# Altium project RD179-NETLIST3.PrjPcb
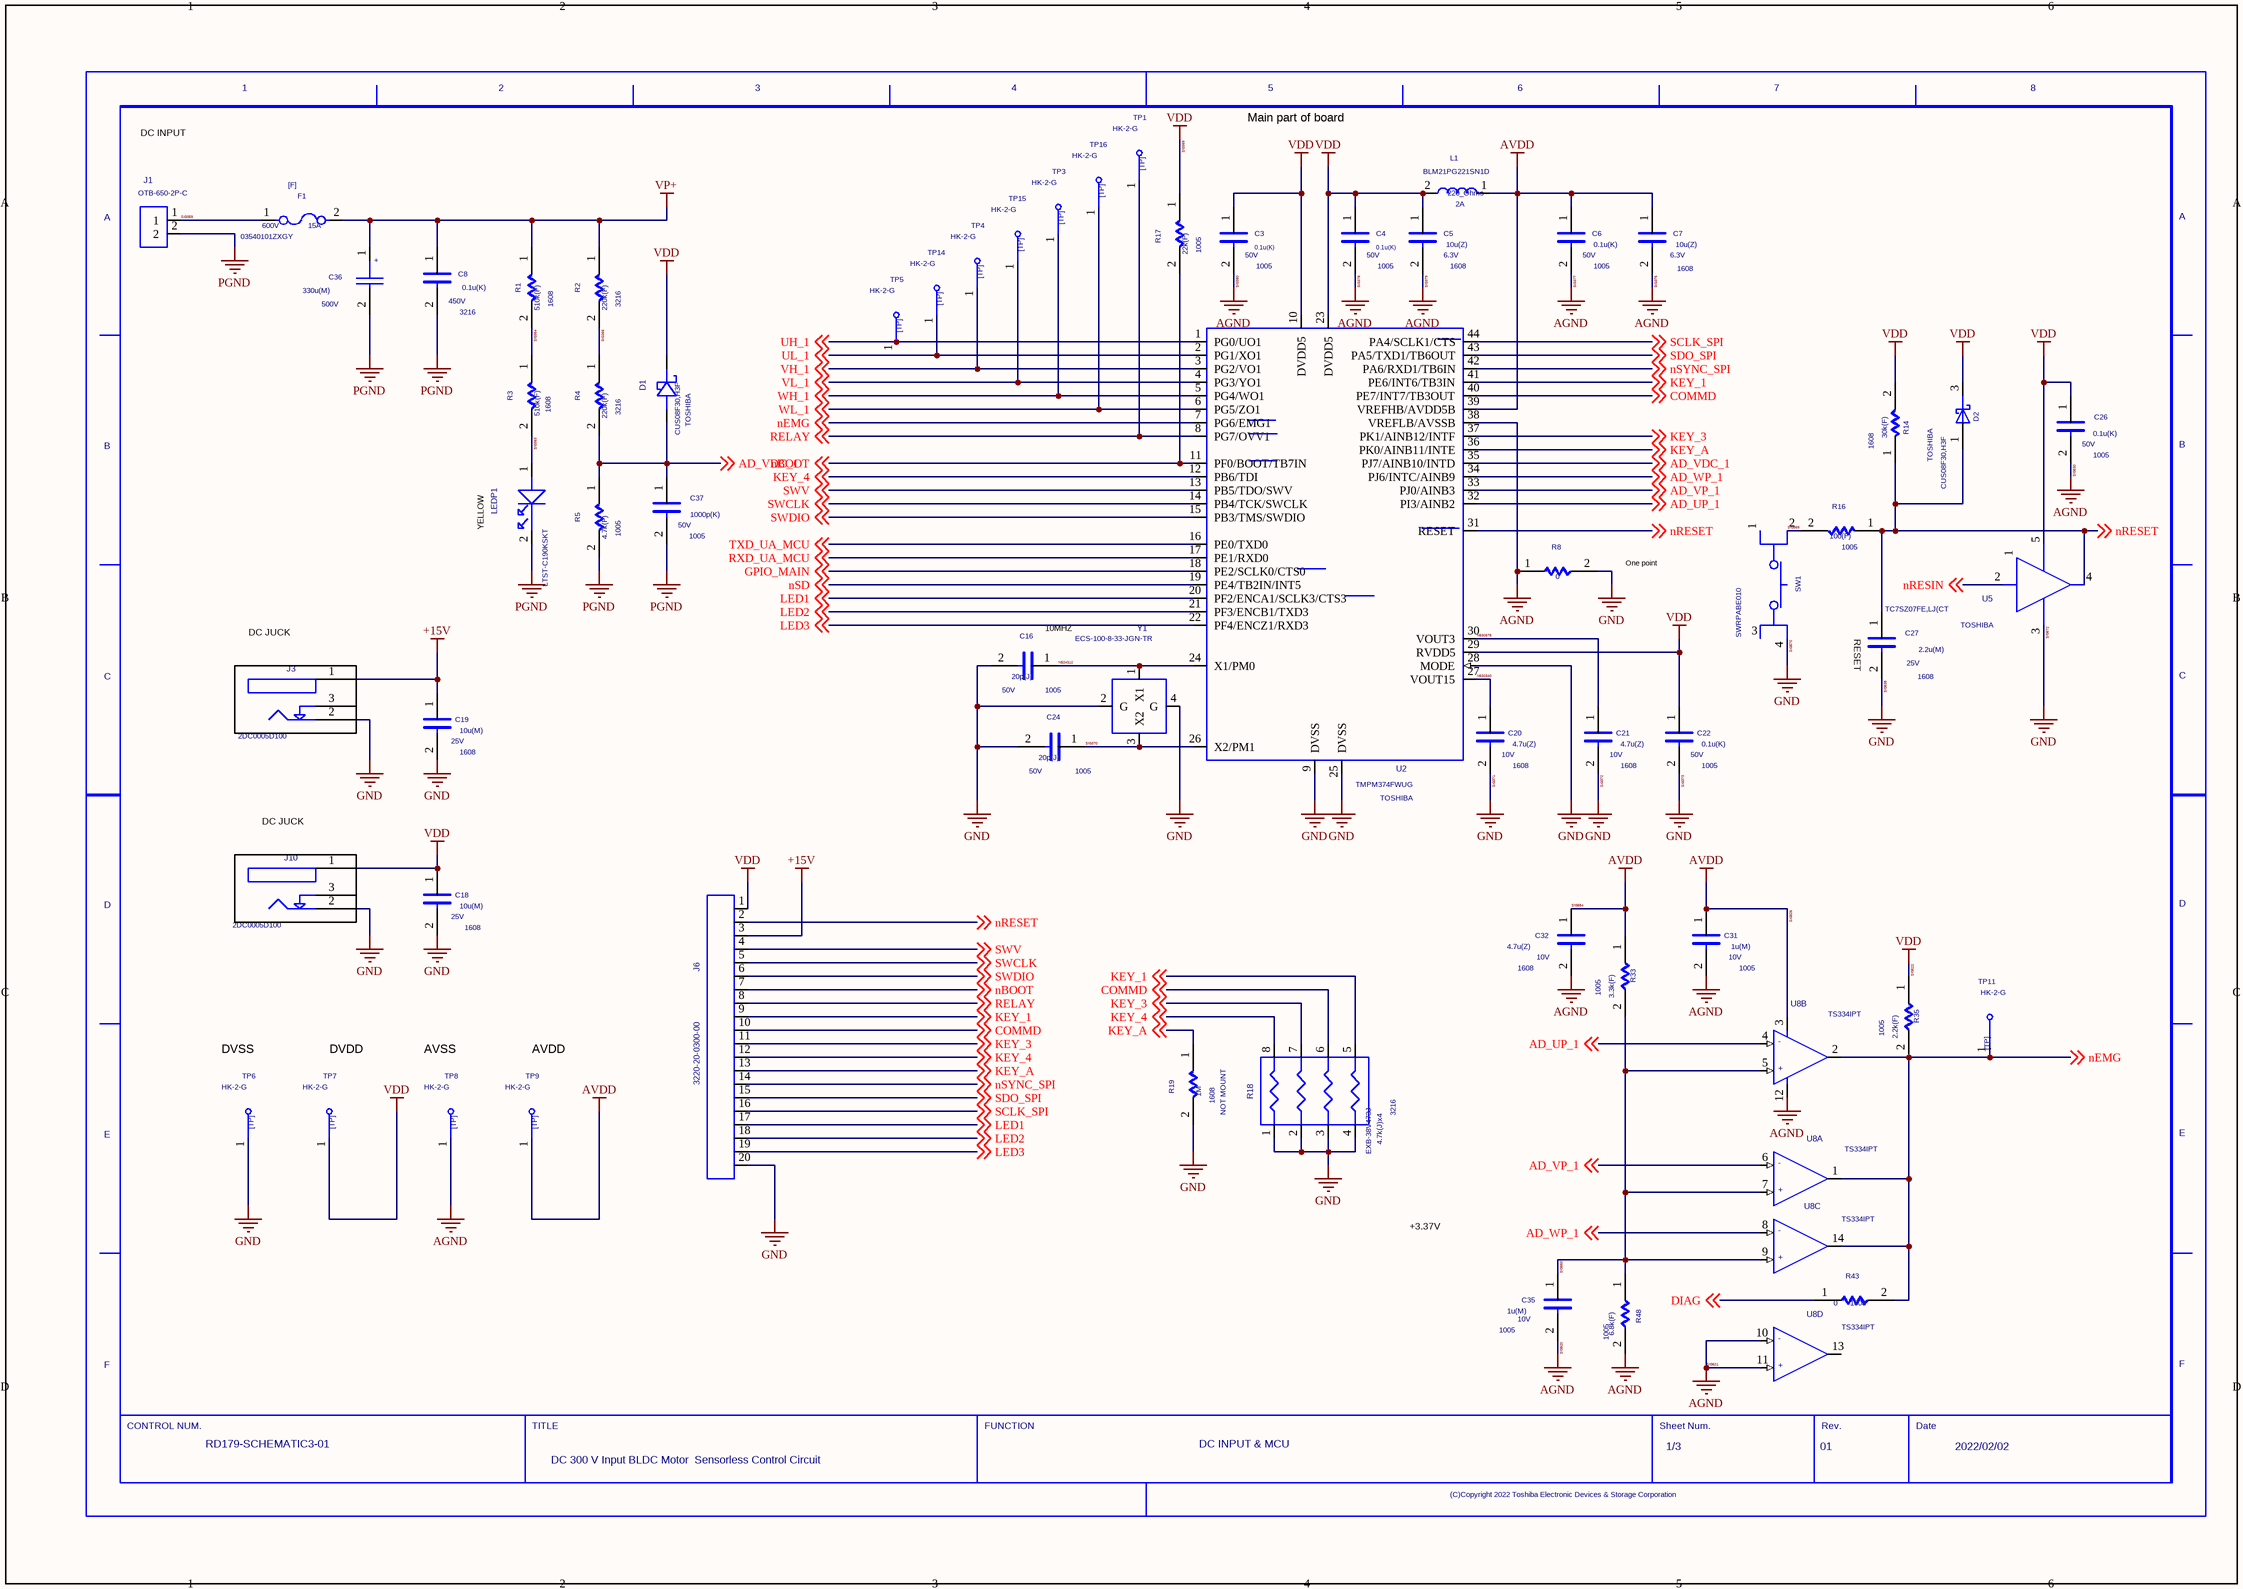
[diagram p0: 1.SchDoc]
3 sheets, 148 parts. Net scope: global (net labels, ports and power ports of the same name join across sheets).
Sheets:
  1.SchDoc
  2.SchDoc
  3.SchDoc

## Sheet 1.SchDoc
size 420 x 297 mm

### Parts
(Parts that share a designator on the sheet are numbered #1, #2 ... from top to bottom, then left to right.)
C3  SIZECODESMD: 1005  VAL2: 50V  VAL1: 0.1u(K)  (hidden comment: C)
C4  SIZECODESMD: 1005  VAL2: 50V  VAL1: 0.1u(K)  (hidden comment: C)
C5  SIZECODESMD: 1608  VAL2: 6.3V  VAL1: 10u(Z)  (hidden comment: C)
C6  SIZECODESMD: 1005  VAL2: 50V  VAL1: 0.1u(K)  (hidden comment: C)
C7  SIZECODESMD: 1608  VAL2: 6.3V  VAL1: 10u(Z)  (hidden comment: C)
C8  SIZECODESMD: 3216  VAL2: 450V  VAL1: 0.1u(K)  (hidden comment: C)
C16  SIZECODESMD: 1005  VAL2: 50V  VAL1: 20p(J)  (hidden comment: C)
C18  SIZECODESMD: 1608  VAL2: 25V  VAL1: 10u(M)  (hidden comment: C)
C19  SIZECODESMD: 1608  VAL2: 25V  VAL1: 10u(M)  (hidden comment: C)
C20  SIZECODESMD: 1608  VAL2: 10V  VAL1: 4.7u(Z)  (hidden comment: C)
C21  SIZECODESMD: 1608  VAL2: 10V  VAL1: 4.7u(Z)  (hidden comment: C)
C22  SIZECODESMD: 1005  VAL2: 50V  VAL1: 0.1u(K)  (hidden comment: C)
C24  SIZECODESMD: 1005  VAL2: 50V  VAL1: 20p(J)  (hidden comment: C)
C26  SIZECODESMD: 1005  VAL2: 50V  VAL1: 0.1u(K)  (hidden comment: C)
C27  SIZECODESMD: 1608  VAL2: 25V  VAL1: 2.2u(M)  (hidden comment: C)
C31  SIZECODESMD: 1005  VAL2: 10V  VAL1: 1u(M)  (hidden comment: C)
C32  SIZECODESMD: 1608  VAL2: 10V  VAL1: 4.7u(Z)  (hidden comment: C)
C35  SIZECODESMD: 1005  VAL2: 10V  VAL1: 1u(M)  (hidden comment: C)
C36  VAL2: 500V  VAL1: 330u(M)  (hidden comment: CP)
C37  SIZECODESMD: 1005  VAL2: 50V  VAL1: 1000p(K)  (hidden comment: C)
D1  USERCOMPTEXT3: TOSHIBA  VAL3: CUS08F30,H3F  (hidden comment: CUS08F30)
D2  USERCOMPTEXT3: TOSHIBA  VAL3: CUS08F30,H3F  (hidden comment: SBD)
F1  VAL3: 03540101ZXGY  VAL2: 15A  VAL1: 600V  (hidden comment: F)
J1  OTB-650-2P-C
J3  VAL3: 2DC0005D100  (hidden comment: DCJACK)
J6  3220-20-0300-00
J10  VAL3: 2DC0005D100  (hidden comment: DCJACK)
L1  VAL3: BLM21PG221SN1D  VAL2: 2A  VAL1: 220_Ohms  (hidden comment: L)
LEDP1  LTST-C190KSKT  [LED]
R1  SIZECODESMD: 1608  VAL1: 510k(F)  (hidden comment: R)
R2  SIZECODESMD: 3216  VAL1: 220k(F)  (hidden comment: R)
R3  SIZECODESMD: 1608  VAL1: 510k(F)  (hidden comment: R)
R4  SIZECODESMD: 3216  VAL1: 220k(F)  (hidden comment: R)
R5  SIZECODESMD: 1005  VAL1: 4.7k(F)  (hidden comment: R)
R8  VAL1: 0  (hidden comment: R)
R14  SIZECODESMD: 1608  VAL1: 30k(F)  (hidden comment: R)
R16  SIZECODESMD: 1005  VAL1: 100(F)  (hidden comment: R)
R17  SIZECODESMD: 1005  VAL1: 22k(F)  (hidden comment: R)
R18  SIZECODESMD: 3216  VAL1: 4.7k(J)x4  (hidden comment: EXB-38V473J)
R19  NOTMOUNT: NOT MOUNT  SIZECODESMD: 1608  VAL1: 1M  (hidden comment: R)
R33  SIZECODESMD: 1005  VAL1: 3.3k(F)  (hidden comment: R)
R35  SIZECODESMD: 1005  VAL1: 2.2k(F)  (hidden comment: R)
R43  SIZECODESMD: 1608  VAL1: 0  (hidden comment: R)
R48  SIZECODESMD: 1005  VAL1: 6.8k(F)  (hidden comment: R)
SW1  SWRPABE010
TP1  VAL3: HK-2-G  (hidden comment: TP)
TP3  VAL3: HK-2-G  (hidden comment: TP)
TP4  VAL3: HK-2-G  (hidden comment: TP)
TP5  VAL3: HK-2-G  (hidden comment: TP)
TP6  VAL3: HK-2-G  (hidden comment: TP)
TP7  VAL3: HK-2-G  (hidden comment: TP)
TP8  VAL3: HK-2-G  (hidden comment: TP)
TP9  VAL3: HK-2-G  (hidden comment: TP)
TP11  VAL3: HK-2-G  (hidden comment: TP)
TP14  VAL3: HK-2-G  (hidden comment: TP)
TP15  VAL3: HK-2-G  (hidden comment: TP)
TP16  VAL3: HK-2-G  (hidden comment: TP)
U2  USERCOMPTEXT3: TOSHIBA  (hidden comment: TMPM374FWUG)
U5  USERCOMPTEXT3: TOSHIBA  VAL3: TC7SZ07FE,LJ(CT  (hidden comment: SN74LVC1G07DRLR_1)
U8  VAL3: TS334IPT  (hidden comment: LMV339IPT_2)  (parts A,B,C,D of 4)
U?#1  DATE: 2022/02/02  FUNCTION: DC INPUT & MCU  TITLE: DC 300 V Input BLDC Motor / Sensorless Control Circuit  DRAWINGNUMBER: RD179-SCHEMATIC3-01  REVISION: 01  SHEETNUMBER: 1/3  (hidden comment: WAKU_DEF100)
Y1  VAL3: ECS-100-8-33-JGN-TR  (hidden comment: XTAL_ECS_100_8_33_10_000MHZ)

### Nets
+15V: C19.1 J3.1(+5V) J6.3  [project net SIG462]
PGND: C8.2 C36.2 C37.2 J1.2 LEDP1.2(Cathode) R5.2  [project net SIG567]
SIG369: C3.1 C4.1 C5.1 C18.1 C22.1 C26.1 D1.3(CATHODE) D2.3(C) J6.1 J10.1(+5V) L1.2 R14.2 R17.1 R35.1 TP7.1 U2.10(DVDD5) U2.23(DVDD5) U2.29(RVDD5) U5.5(VCC)  [also labelled SIG522, VDD]
SIG371: C16.2 C18.2 C19.2 C20.2 C21.2 C22.2 C24.2 C27.2 J3.2(GND) J6.20 J10.2(GND) R8.2 R18.1 R18.2 R18.3 R18.4 R19.2 SW1.4 TP6.1 U2.9(DVSS) U2.25(DVSS) U2.28(MODE) U5.3(GND) Y1.2(G) Y1.4(G)  [also labelled GND, SIG372, SIG373, SIG535, SIG570, SIG572]
SIG376: C3.2 C4.2 C5.2 C6.2 C7.2 C26.2 C31.2 C32.2 C35.2 R8.1 R48.2 TP8.1 U2.38(VREFLB/AVSSB) U8.10 U8.11 U8.12(GND)  [also labelled AGND, SIG377, SIG378, SIG379, SIG380, SIG520, SIG521, SIG530]
SIG526: C6.1 C7.1 C31.1 C32.1 L1.1 R33.1 TP9.1 U2.39(VREFHB/AVDD5B) U8.3(VCC)  [also labelled AVDD, SIG554]
VP+: C8.1 C36.1 F1.2 R1.1 R2.1  [project net SIG477]
AD_UP_1: U2.32(PI3/AINB2) U8.4(IN-) ; off-sheet AD_UP_1
AD_VDC_1: C37.1 D1.1(ANODE) R4.2 R5.1 U2.35(PJ7/AINB10/INTD) ; off-sheet AD_VDC_1
AD_VP_1: U2.33(PJ0/AINB3) U8.6 ; off-sheet AD_VP_1
AD_WP_1: U2.34(PJ6/INTC/AINB9) U8.8 ; off-sheet AD_WP_1
COMMD: J6.10 R18.6 U2.40(PE7/INT7/TB3OUT) ; off-sheet COMMD
DIAG: R43.1 ; off-sheet DIAG
GPIO_MAIN: U2.18(PE2/SCLK0/CTS0) ; off-sheet GPIO_MAIN
KEY_1: J6.9 R18.5 U2.41(PE6/INT6/TB3IN) ; off-sheet KEY_1
KEY_3: J6.11 R18.7 U2.37(PK1/AINB12/INTF) ; off-sheet KEY_3
KEY_4: J6.12 R18.8 U2.12(PB6/TDI) ; off-sheet KEY_4
KEY_A: J6.13 R19.1 U2.36(PK0/AINB11/INTE) ; off-sheet KEY_A
LED1: J6.17 U2.20(PF2/ENCA1/SCLK3/CTS3) ; off-sheet LED1
LED2: J6.18 U2.21(PF3/ENCB1/TXD3) ; off-sheet LED2
LED3: J6.19 U2.22(PF4/ENCZ1/RXD3) ; off-sheet LED3
N524312: C16.1 U2.24(X1/PM0) Y1.1(X1)
N530340: C20.1 U2.27(VOUT15)
N530678: C21.1 U2.30(VOUT3)
nBOOT: J6.7 R17.2 U2.11(PF0/BOOT/TB7IN) ; off-sheet nBOOT
nEMG: R35.2 R43.2 TP11.1 U2.7(PG6/EMG1) U8.1 U8.2(OUT) U8.14 ; off-sheet nEMG
nRESET: C27.1 D2.1(A) J6.2 R14.1 R16.1 U2.31(RESET) U5.4(OUTY) ; off-sheet nRESET
nSD: U2.19(PE4/TB2IN/INT5) ; off-sheet nSD
nSYNC_SPI: J6.14 U2.42(PA6/RXD1/TB6IN) ; off-sheet nSYNC_SPI
RELAY: J6.8 TP1.1 U2.8(PG7/OVV1) ; off-sheet RELAY
RXD_UA_MCU: U2.17(PE1/RXD0) ; off-sheet RXD_UA_MCU
SCLK_SPI: J6.16 U2.44(PA4/SCLK1/CTS) ; off-sheet SCLK_SPI
SDO_SPI: J6.15 U2.43(PA5/TXD1/TB6OUT) ; off-sheet SDO_SPI
SIG359: F1.1 J1.1
SIG363: LEDP1.1(Anode) R3.2
SIG364: R1.2 R3.1
SIG366: R2.2 R4.1
SIG370: C24.1 U2.26(X2/PM1) Y1.3(X2)
SIG553: C35.1 R33.2 R48.1 U8.5(IN+) U8.7 U8.9
SIG569: R16.2 SW1.2
SIG571: U5.2(INA) ; off-sheet nRESIN  [also labelled nRESIN]
SWCLK: J6.5 U2.14(PB4/TCK/SWCLK) ; off-sheet SWCLK
SWDIO: J6.6 U2.15(PB3/TMS/SWDIO) ; off-sheet SWDIO
SWV: J6.4 U2.13(PB5/TDO/SWV) ; off-sheet SWV
TXD_UA_MCU: U2.16(PE0/TXD0) ; off-sheet TXD_UA_MCU
UH_1: TP5.1 U2.1(PG0/UO1) ; off-sheet UH_1
UL_1: TP14.1 U2.2(PG1/XO1) ; off-sheet UL_1
VH_1: TP4.1 U2.3(PG2/VO1) ; off-sheet VH_1
VL_1: TP15.1 U2.4(PG3/YO1) ; off-sheet VL_1
WH_1: TP3.1 U2.5(PG4/WO1) ; off-sheet WH_1
WL_1: TP16.1 U2.6(PG5/ZO1) ; off-sheet WL_1

Not connected (* = marked no-connect by the designer): J3 3(NC); J10 3(NC); SW1 1 3; U5 1; U8 13

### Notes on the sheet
- Main part of board
- DC INPUT
  120V-340V
- (near LEDP1) YELLOW
- One point
  ground
- (near J3) DC JUCK
  +15V
- (near C16) 10MHZ
- (near C27) RESET
- (near J10) DC JUCK
  +5V
- DVSS
- DVDD
- AVSS
- AVDD
- +3.37V
  (2.89A)

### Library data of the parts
C3 C4 C6 C16 C22 C24 C26 C31 C35 C37 = C: OriginalSymbolOrigin: (2540,7620); COMP: CRC-1005-DEF
C5 C7 C18-C21 C27 C32 = C: OriginalSymbolOrigin: (2540,7620); COMP: CRC-1608-DEF
C8 = C: OriginalSymbolOrigin: (2540,7620); COMP: CC-3216-DEF
C36 = CP: SAVEAREA0: -1450,-153,20294,13055; SAVECOUNT: 52; TIME: 15:02:55; UPDATEUSER: fukuda-y; UPDATETIME: 16:13:42; OriginalSymbolOrigin: (2540,10160); COMP: DDC-3000-00
D1 = DIODE_SB1003M3: COMP: CD-USC-05; TIME: 16:32:01; UPDATEUSER: t5459927; SAVECOUNT: 1; OriginalSymbolOrigin: (0,0); INSTANCENAME: I16849034
D2 = SBD: SAVEAREA0: -4630,-153,17114,13055; TIME: 14:49:55; UPDATEUSER: fukuda-y; UPDATETIME: 08:16:22; SAVECOUNT: 9; OriginalSymbolOrigin: (5080,5080); COMP: CD-USC-05
F1 = F: OriginalSymbolOrigin: (2540,5080); COMP: DFU-3512-00
J1 = OTB_650_2P_C: COMP: OTB-650-2P_R00; TIME: 16:32:00; UPDATEUSER: t5459927; SAVECOUNT: 1; SAVEAREA0: -4443,-7788,6738,409; OriginalSymbolOrigin: (0,0); INSTANCENAME: I00689
J3 = DCJACK: COMP: 2DC-0005D100_R00; ORDER: 0; TIME: 16:32:01; UPDATEUSER: t5459927; SAVECOUNT: 1; SAVEAREA0: -1163,-13964,20286,1761; OriginalSymbolOrigin: (0,0); INSTANCENAME: I16855658
J6 = CON20: COMP: 3220-20-0300-00_R00; TIME: 16:32:01; UPDATEUSER: t5459927; SAVECOUNT: 1; SAVEAREA0: -36272,-54408,42011,2984; OriginalSymbolOrigin: (0,0); INSTANCENAME: I17020784
J10 = DCJACK: COMP: 2DC-0005D100_R00; ORDER: 0; TIME: 16:32:01; UPDATEUSER: t5459927; SAVECOUNT: 1; SAVEAREA0: -1163,-13964,20286,1761; OriginalSymbolOrigin: (0,0); INSTANCENAME: I17047111
L1 = L: OriginalSymbolOrigin: (2540,5080); COMP: CL-2125-DEF
LEDP1 = LED_3RED: COMP: LTST-C190_R00; TIME: 16:32:00; UPDATEUSER: t5459927; SAVECOUNT: 1; OriginalSymbolOrigin: (0,0); INSTANCENAME: I16843725
R1 R3 = R: OriginalSymbolOrigin: (5080,5080); VAL2: 250mW; COMP: CRC-1608-DEF
R2 R4 = R: OriginalSymbolOrigin: (5080,5080); VAL2: 250mW; COMP: CR-3216-DEF
R5 = R: OriginalSymbolOrigin: (5080,5080); VAL2: 63mW; COMP: CRC-1005-DEF
R8 = R: OriginalSymbolOrigin: (5080,5080); COMP: CX-0002-75
R14 = R: OriginalSymbolOrigin: (5080,5080); VAL2: 100mW; COMP: CRC-1608-58
R16 R17 R33 R35 = R: OriginalSymbolOrigin: (5080,5080); VAL2: 100mW; COMP: CRC-1005-DEF
R18 = EXB_38V: COMP: CRA-3216-33; TIME: 16:32:00; UPDATEUSER: t5459927; SAVECOUNT: 1; SAVEAREA0: -8920,-20726,20901,1136; OriginalSymbolOrigin: (0,0); VAL2: 63w; INSTANCENAME: I17038151
R19 R43 = R: OriginalSymbolOrigin: (5080,5080); VAL2: 100mW; COMP: CRC-1608-DEF
R48 = R: OriginalSymbolOrigin: (5080,5080); VAL2: 63mW; COMP: CRC-1005-12
SW1 = SWRPABE010: CDBNAME: S3; MONOCODE: E00000387; DEVICENAME: SKRELEE010; SAVECOUNT: 12; SAVEAREA0: -20086,-19151,40623,8833; TIME: 17:27:08; UPDATEUSER: t5459927; UPDATETIME: 11:11:13; OriginalSymbolOrigin: (-2540,-2540); COMP: SKRPABE010_R01
TP1 TP3-TP9 TP11 TP14-TP16 = TP: TIME: 16:12:21; UPDATEUSER: fukuda-y; UPDATETIME: 16:18:11; SAVECOUNT: 2; SAVEAREA0: -242,-92,12810,7836; OriginalSymbolOrigin: (0,7620)
U2 = TMPM374FWUG: TIME: 16:32:00; UPDATEUSER: t5459927; UPDATETIME: 15:11:09; SAVECOUNT: 3; SAVEAREA0: -44310,-81679,90078,-7285; OriginalSymbolOrigin: (0,0)
U5 = SN74LVC1G07DRLR_1: COMP: TC7SZ07FE; ORDER: 0; TIME: 16:32:01; UPDATEUSER: t5459927; UPDATETIME: 09:28:13; SAVECOUNT: 2; SAVEAREA0: -35105,-23290,44922,13600; OriginalSymbolOrigin: (-2540,2540)
U8 = LMV339IPT_2: TIME: 16:31:59; UPDATEUSER: t5459927; UPDATETIME: 15:18:09; SAVECOUNT: 11; SAVEAREA0: -12314,3023,22191,18929; OriginalSymbolOrigin: (0,0); CaptureCellPackProp: LMV339IPT_2A; FUNCN: TS334IPT_2
U?#1 = WAKU_DEF100: PLOTTIME: HH:MM; SAVEAREA0: 147884,-66467,487065,89883; TIME: 14:30:25; UPDATEUSER: t5459927; UPDATETIME: 12:53:04; SAVECOUNT: 7; OriginalSymbolOrigin: (10160,284480)
Y1 = XTAL_ECS_100_8_33_10_000MHZ: COMP: CXL-3225-68; ORDER: 1; TIME: 16:32:00; UPDATEUSER: t5459927; UPDATETIME: 15:12:21; SAVECOUNT: 3; SAVEAREA0: -55012,-32573,65020,22757; OriginalSymbolOrigin: (0,0)

## Sheet 2.SchDoc
size 420 x 297 mm
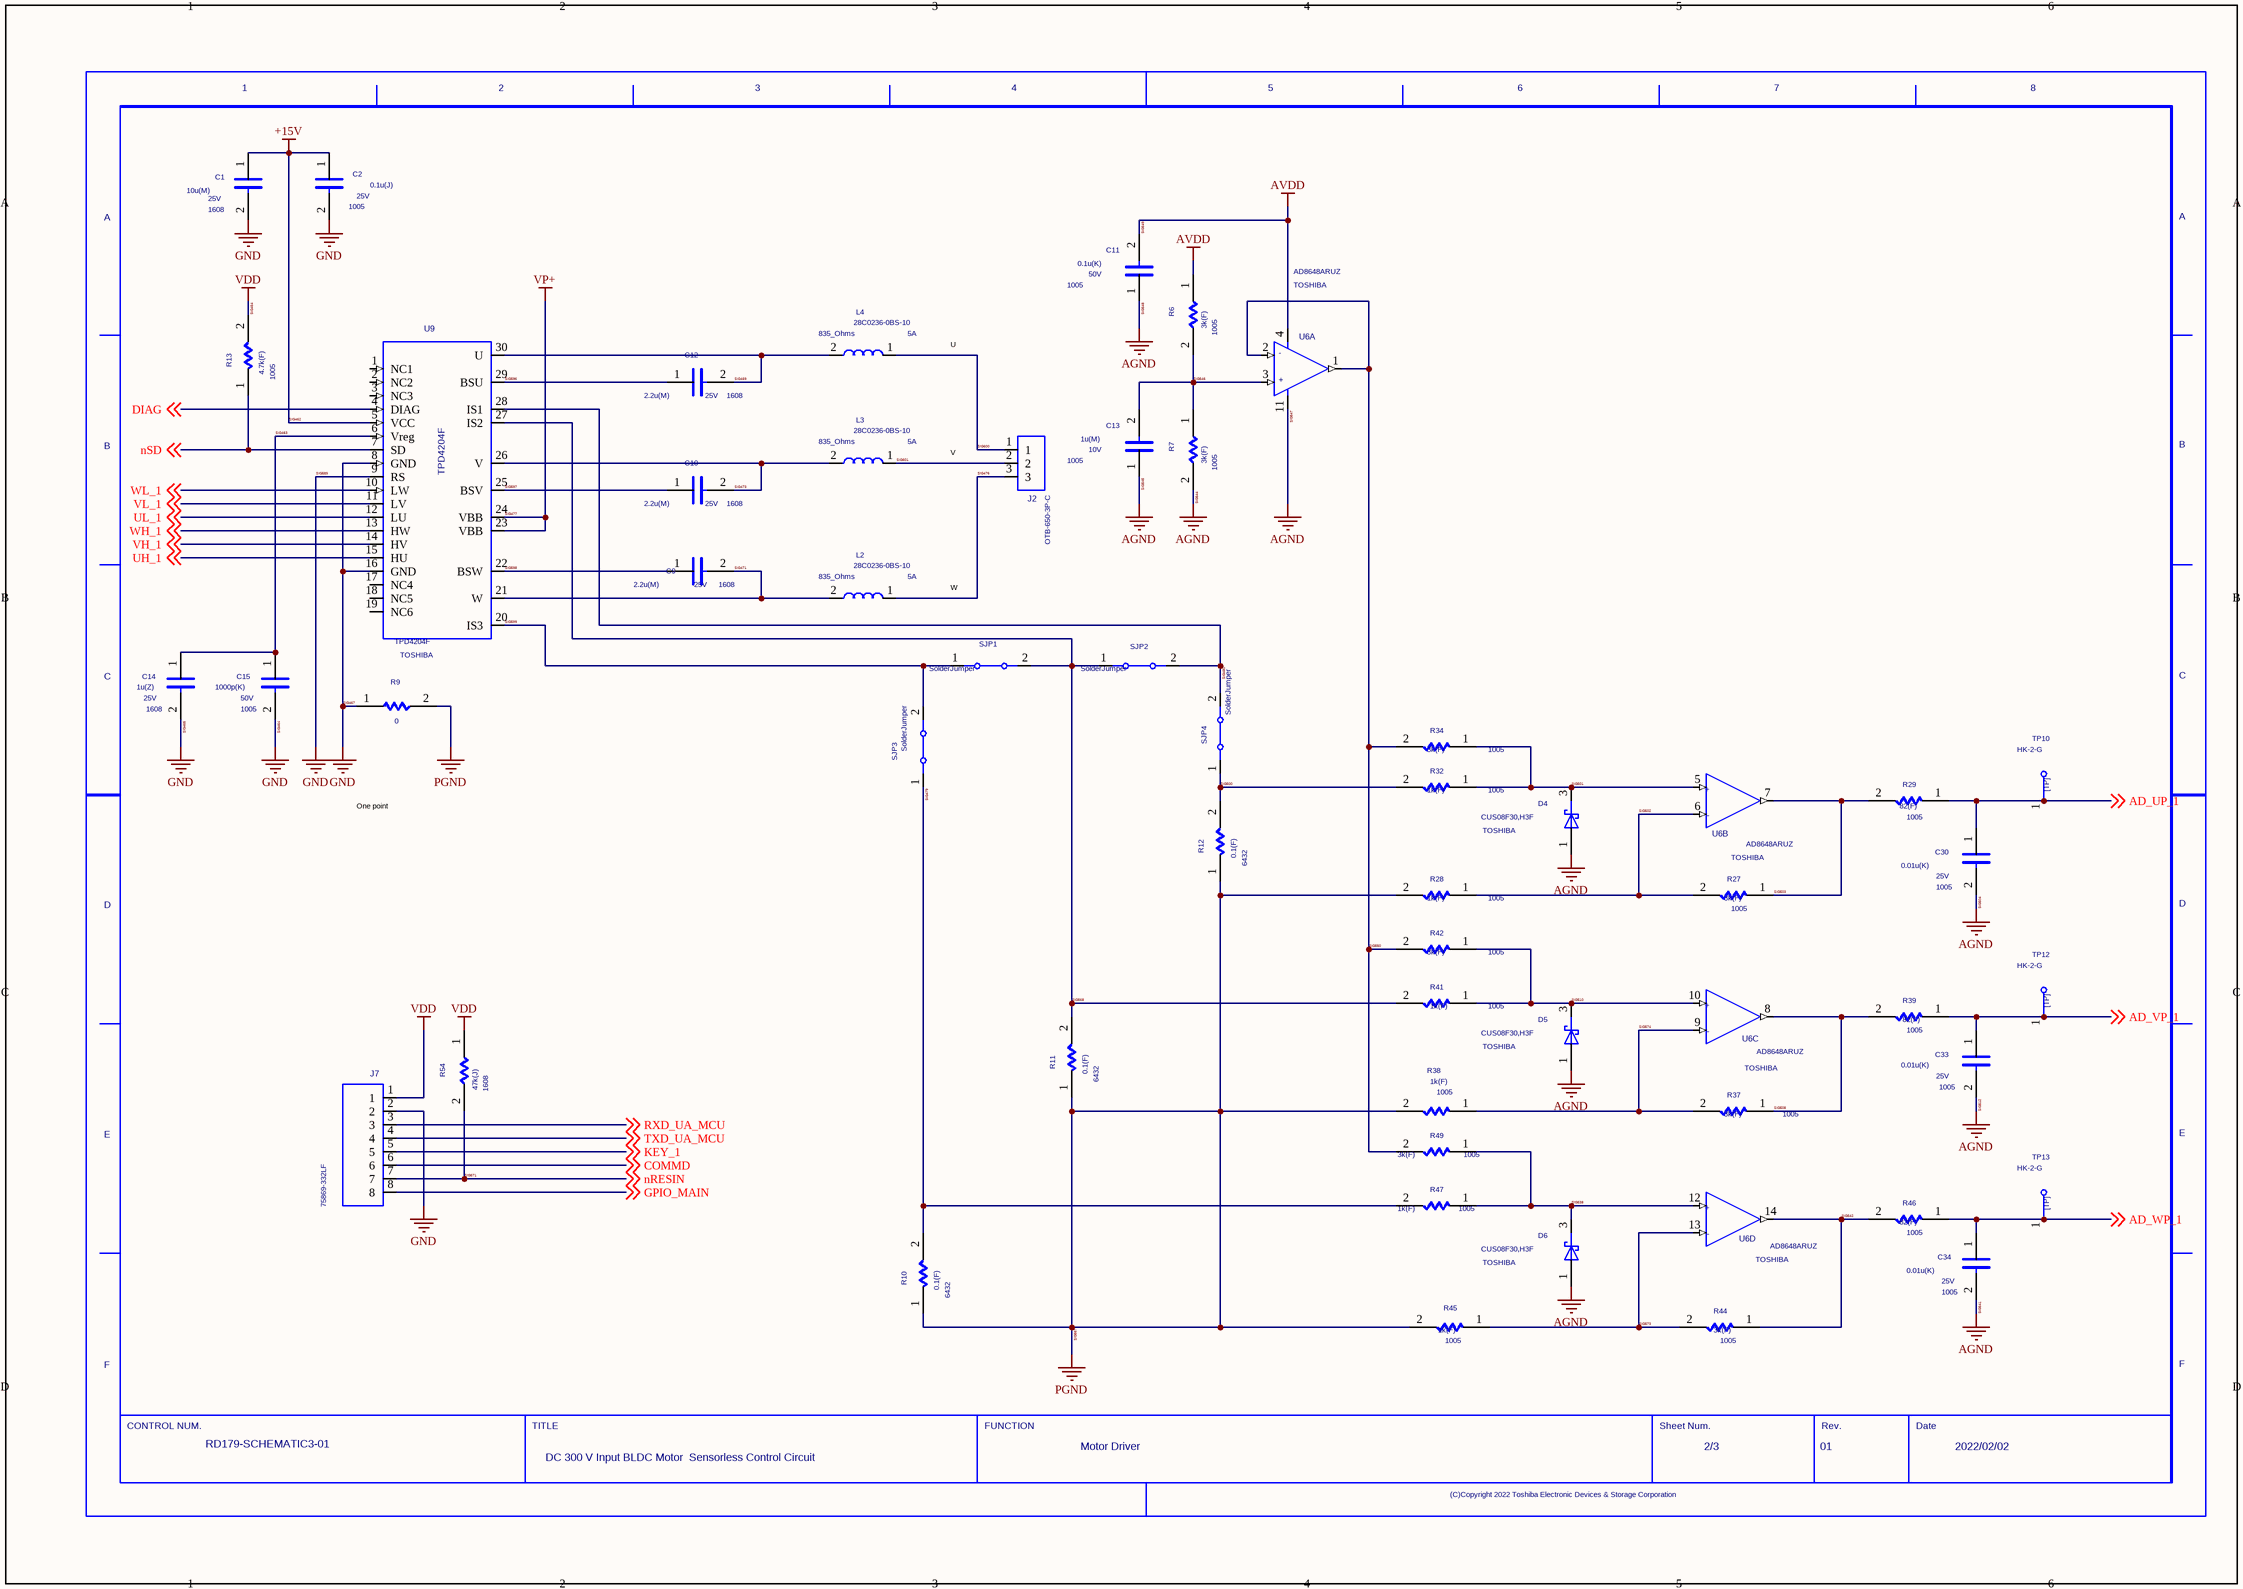
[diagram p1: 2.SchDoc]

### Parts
(Parts that share a designator on the sheet are numbered #1, #2 ... from top to bottom, then left to right.)
C1  SIZECODESMD: 1608  VAL2: 25V  VAL1: 10u(M)  (hidden comment: C)
C2  SIZECODESMD: 1005  VAL2: 25V  VAL1: 0.1u(J)  (hidden comment: C)
C9  SIZECODESMD: 1608  VAL2: 25V  VAL1: 2.2u(M)  (hidden comment: C)
C10  SIZECODESMD: 1608  VAL2: 25V  VAL1: 2.2u(M)  (hidden comment: C)
C11  SIZECODESMD: 1005  VAL2: 50V  VAL1: 0.1u(K)  (hidden comment: C)
C12  SIZECODESMD: 1608  VAL2: 25V  VAL1: 2.2u(M)  (hidden comment: C)
C13  SIZECODESMD: 1005  VAL2: 10V  VAL1: 1u(M)  (hidden comment: C)
C14  SIZECODESMD: 1608  VAL2: 25V  VAL1: 1u(Z)  (hidden comment: C)
C15  SIZECODESMD: 1005  VAL2: 50V  VAL1: 1000p(K)  (hidden comment: C)
C30  SIZECODESMD: 1005  VAL2: 25V  VAL1: 0.01u(K)  (hidden comment: C)
C33  SIZECODESMD: 1005  VAL2: 25V  VAL1: 0.01u(K)  (hidden comment: C)
C34  SIZECODESMD: 1005  VAL2: 25V  VAL1: 0.01u(K)  (hidden comment: C)
D4  USERCOMPTEXT3: TOSHIBA  VAL3: CUS08F30,H3F  (hidden comment: SBD)
D5  USERCOMPTEXT3: TOSHIBA  VAL3: CUS08F30,H3F  (hidden comment: SBD)
D6  USERCOMPTEXT3: TOSHIBA  VAL3: CUS08F30,H3F  (hidden comment: SBD)
J2  OTB-650-3P-C
J7  75869-332LF
L2  VAL3: 28C0236-0BS-10  VAL2: 5A  VAL1: 835_Ohms  (hidden comment: L)
L3  VAL3: 28C0236-0BS-10  VAL2: 5A  VAL1: 835_Ohms  (hidden comment: L)
L4  VAL3: 28C0236-0BS-10  VAL2: 5A  VAL1: 835_Ohms  (hidden comment: L)
R6  SIZECODESMD: 1005  VAL1: 3k(F)  (hidden comment: R)
R7  SIZECODESMD: 1005  VAL1: 3k(F)  (hidden comment: R)
R9  VAL1: 0  (hidden comment: R)
R10  SIZECODESMD: 6432  VAL1: 0.1(F)  (hidden comment: R)
R11  SIZECODESMD: 6432  VAL1: 0.1(F)  (hidden comment: R)
R12  SIZECODESMD: 6432  VAL1: 0.1(F)  (hidden comment: R)
R13  SIZECODESMD: 1005  VAL1: 4.7k(F)  (hidden comment: R)
R27  SIZECODESMD: 1005  VAL1: 3k(F)  (hidden comment: R)
R28  SIZECODESMD: 1005  VAL1: 1k(F)  (hidden comment: R)
R29  SIZECODESMD: 1005  VAL1: 82(F)  (hidden comment: R)
R32  SIZECODESMD: 1005  VAL1: 1k(F)  (hidden comment: R)
R34  SIZECODESMD: 1005  VAL1: 3k(F)  (hidden comment: R)
R37  SIZECODESMD: 1005  VAL1: 3k(F)  (hidden comment: R)
R38  SIZECODESMD: 1005  VAL1: 1k(F)  (hidden comment: R)
R39  SIZECODESMD: 1005  VAL1: 82(F)  (hidden comment: R)
R41  SIZECODESMD: 1005  VAL1: 1k(F)  (hidden comment: R)
R42  SIZECODESMD: 1005  VAL1: 3k(F)  (hidden comment: R)
R44  SIZECODESMD: 1005  VAL1: 3k(F)  (hidden comment: R)
R45  SIZECODESMD: 1005  VAL1: 1k(F)  (hidden comment: R)
R46  SIZECODESMD: 1005  VAL1: 82(F)  (hidden comment: R)
R47  SIZECODESMD: 1005  VAL1: 1k(F)  (hidden comment: R)
R49  SIZECODESMD: 1005  VAL1: 3k(F)  (hidden comment: R)
R54  SIZECODESMD: 1608  VAL1: 47k(J)  (hidden comment: R)
SJP1  VAL3: SolderJumper  (hidden comment: JP)
SJP2  VAL3: SolderJumper  (hidden comment: JP)
SJP3  VAL3: SolderJumper  (hidden comment: JP)
SJP4  VAL3: SolderJumper  (hidden comment: JP)
TP10  VAL3: HK-2-G  (hidden comment: TP)
TP12  VAL3: HK-2-G  (hidden comment: TP)
TP13  VAL3: HK-2-G  (hidden comment: TP)
U6  USERCOMPTEXT3: TOSHIBA  VAL3: AD8648ARUZ  (hidden comment: AD8648ARUZ_1)  (parts A,B,C,D of 4)
U9  USERCOMPTEXT3: TOSHIBA  (hidden comment: TPD4204F)
U?#2  DATE: 2022/02/02  TITLE: DC 300 V Input BLDC Motor / Sensorless Control Circuit  FUNCTION: Motor Driver  REVISION: 01  SHEETNUMBER: 2/3  DRAWINGNUMBER: RD179-SCHEMATIC3-01  (hidden comment: WAKU_DEF100)

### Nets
AGND: C11.1 C13.1 C30.2 C33.2 C34.2 D4.1(A) D5.1(A) D6.1(A) R7.2 U6.11(GND)  [also labelled SIG504, SIG512, SIG541, SIG544, SIG545, SIG547, SIG548]  [project net SIG376]
AVDD: C11.2 R6.1 U6.4(VCC)  [also labelled SIG549]  [project net SIG526]
GND: C1.2 C2.2 C14.2 C15.2 J7.2 R9.1 U9.8(GND) U9.9(RS) U9.16(GND)  [also labelled SIG464, SIG465, SIG467, SIG589]  [project net SIG371]
SIG454: J7.1 R13.2 R54.1  [also labelled VDD]  [project net SIG369]
SIG462: C1.1 C2.1 U9.5(VCC)  [also labelled +15V]
SIG477: U9.23(VBB) U9.24(VBB)  [also labelled VP+]
SIG567: R9.2 R10.1 R11.1 R12.1 R28.2 R38.2 R45.2  [also labelled PGND]
AD_UP_1: C30.1 R29.1 TP10.1 ; off-sheet AD_UP_1
AD_VP_1: C33.1 R39.1 TP12.1 ; off-sheet AD_VP_1
AD_WP_1: C34.1 R46.1 TP13.1 ; off-sheet AD_WP_1
COMMD: J7.6 ; off-sheet COMMD
DIAG: U9.4(DIAG) ; off-sheet DIAG
GPIO_MAIN: J7.8 ; off-sheet GPIO_MAIN
KEY_1: J7.5 ; off-sheet KEY_1
nSD: R13.1 U9.7(SD) ; off-sheet nSD
RXD_UA_MCU: J7.3 ; off-sheet RXD_UA_MCU
SIG463: C14.1 C15.1 U9.6(Vreg)
SIG469: C12.2 L4.2 U9.30(U)
SIG471: C9.2 L2.2 U9.21(W)
SIG473: C10.2 L3.2 U9.26(V)
SIG476: J2.3 L2.1
SIG479: R10.2 R47.2 SJP3.1
SIG480: SJP2.2 SJP4.2 U9.28(IS1)
SIG500: R12.2 R32.2 SJP4.1
SIG501: D4.3(C) R32.1 R34.1 U6.5
SIG502: R27.2 R28.1 U6.6
SIG503: R27.1 R29.2 U6.7
SIG508: R37.1 R39.2 U6.8
SIG510: D5.3(C) R41.1 R42.1 U6.10
SIG538: D6.3(C) R47.1 R49.1 U6.12
SIG542: R44.1 R46.2 U6.14
SIG546: C13.2 R6.2 R7.1 U6.3(IN+)
SIG550: R34.2 R42.2 R49.2 U6.1(OUT) U6.2(IN-)
SIG568: R11.2 R41.2 SJP1.2 SJP2.1 U9.27(IS2)
SIG571: J7.7 R54.2 ; off-sheet nRESIN  [also labelled nRESIN]
SIG573: R44.2 R45.1 U6.13
SIG574: R37.2 R38.1 U6.9
SIG596: C12.1 U9.29(BSU)
SIG597: C10.1 U9.25(BSV)
SIG598: C9.1 U9.22(BSW)
SIG599: SJP1.1 SJP3.2 U9.20(IS3)
SIG600: J2.1 L4.1
SIG601: J2.2 L3.1
TXD_UA_MCU: J7.4 ; off-sheet TXD_UA_MCU
UH_1: U9.15(HU) ; off-sheet UH_1
UL_1: U9.12(LU) ; off-sheet UL_1
VH_1: U9.14(HV) ; off-sheet VH_1
VL_1: U9.11(LV) ; off-sheet VL_1
WH_1: U9.13(HW) ; off-sheet WH_1
WL_1: U9.10(LW) ; off-sheet WL_1

Not connected (* = marked no-connect by the designer): U9 1(NC1) 2(NC2) 3(NC3) 17(NC4) 18(NC5) 19(NC6)

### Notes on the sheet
- U
- V
- W
- One point
  ground

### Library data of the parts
C1 C9 C10 C12 C14 = C: as C5 on sheet 1
C2 C11 C13 C15 C30 C33 C34 = C: as C3 on sheet 1
D4-D6 = SBD: as D2 on sheet 1
J2 = OTB_650_3P_C: COMP: OTB-650-3P_R00; TIME: 16:31:59; UPDATEUSER: t5459927; SAVECOUNT: 1; SAVEAREA0: -6361,-10384,8548,546; OriginalSymbolOrigin: (0,0); INSTANCENAME: I541179
J7 = CON8: COMP: 75869-332LF_R00; ORDER: 0; TIME: 16:31:59; UPDATEUSER: t5459927; SAVECOUNT: 1; SAVEAREA0: -14610,-23317,18939,1279; OriginalSymbolOrigin: (0,0); INSTANCENAME: I16797633
L2-L4 = L: OriginalSymbolOrigin: (2540,5080); COMP: DL-1460-01
R6 R7 R27 R28 R32 R34 R37 R38 R41 R42 R44 R45 R47 R49 = R: as R16 on sheet 1
R9 = R: as R8 on sheet 1
R10-R12 = R: OriginalSymbolOrigin: (5080,5080); VAL2: 3W; COMP: CR-6432-18
R13 R29 R39 R46 = R: as R5 on sheet 1
R54 = R: as R19 on sheet 1
SJP1-SJP4 = JP: OriginalSymbolOrigin: (2540,5080); COMP: CJP-0002-116
TP10 TP12 TP13 = TP: as TP1 on sheet 1
U6 = AD8648ARUZ_1: TIME: 16:31:59; UPDATEUSER: t5459927; UPDATETIME: 15:23:55; SAVECOUNT: 10; OriginalSymbolOrigin: (0,0); SAVEAREA0: -20143,-23389,30103,13502; CaptureCellPackProp: AD8648ARUZ_1A
U9 = TPD4204F: TIME: 16:32:01; UPDATEUSER: t5459927; UPDATETIME: 10:39:27; SAVECOUNT: 6; SAVEAREA0: -38352,-57023,57455,-16941; OriginalSymbolOrigin: (0,0)
U?#2 = WAKU_DEF100: PLOTTIME: HH:MM; SAVEAREA0: 147884,-66467,487065,89883; TIME: 14:30:25; UPDATEUSER: t5459927; UPDATETIME: 11:31:06; SAVECOUNT: 7; OriginalSymbolOrigin: (10160,284480)

## Sheet 3.SchDoc
size 420 x 297 mm
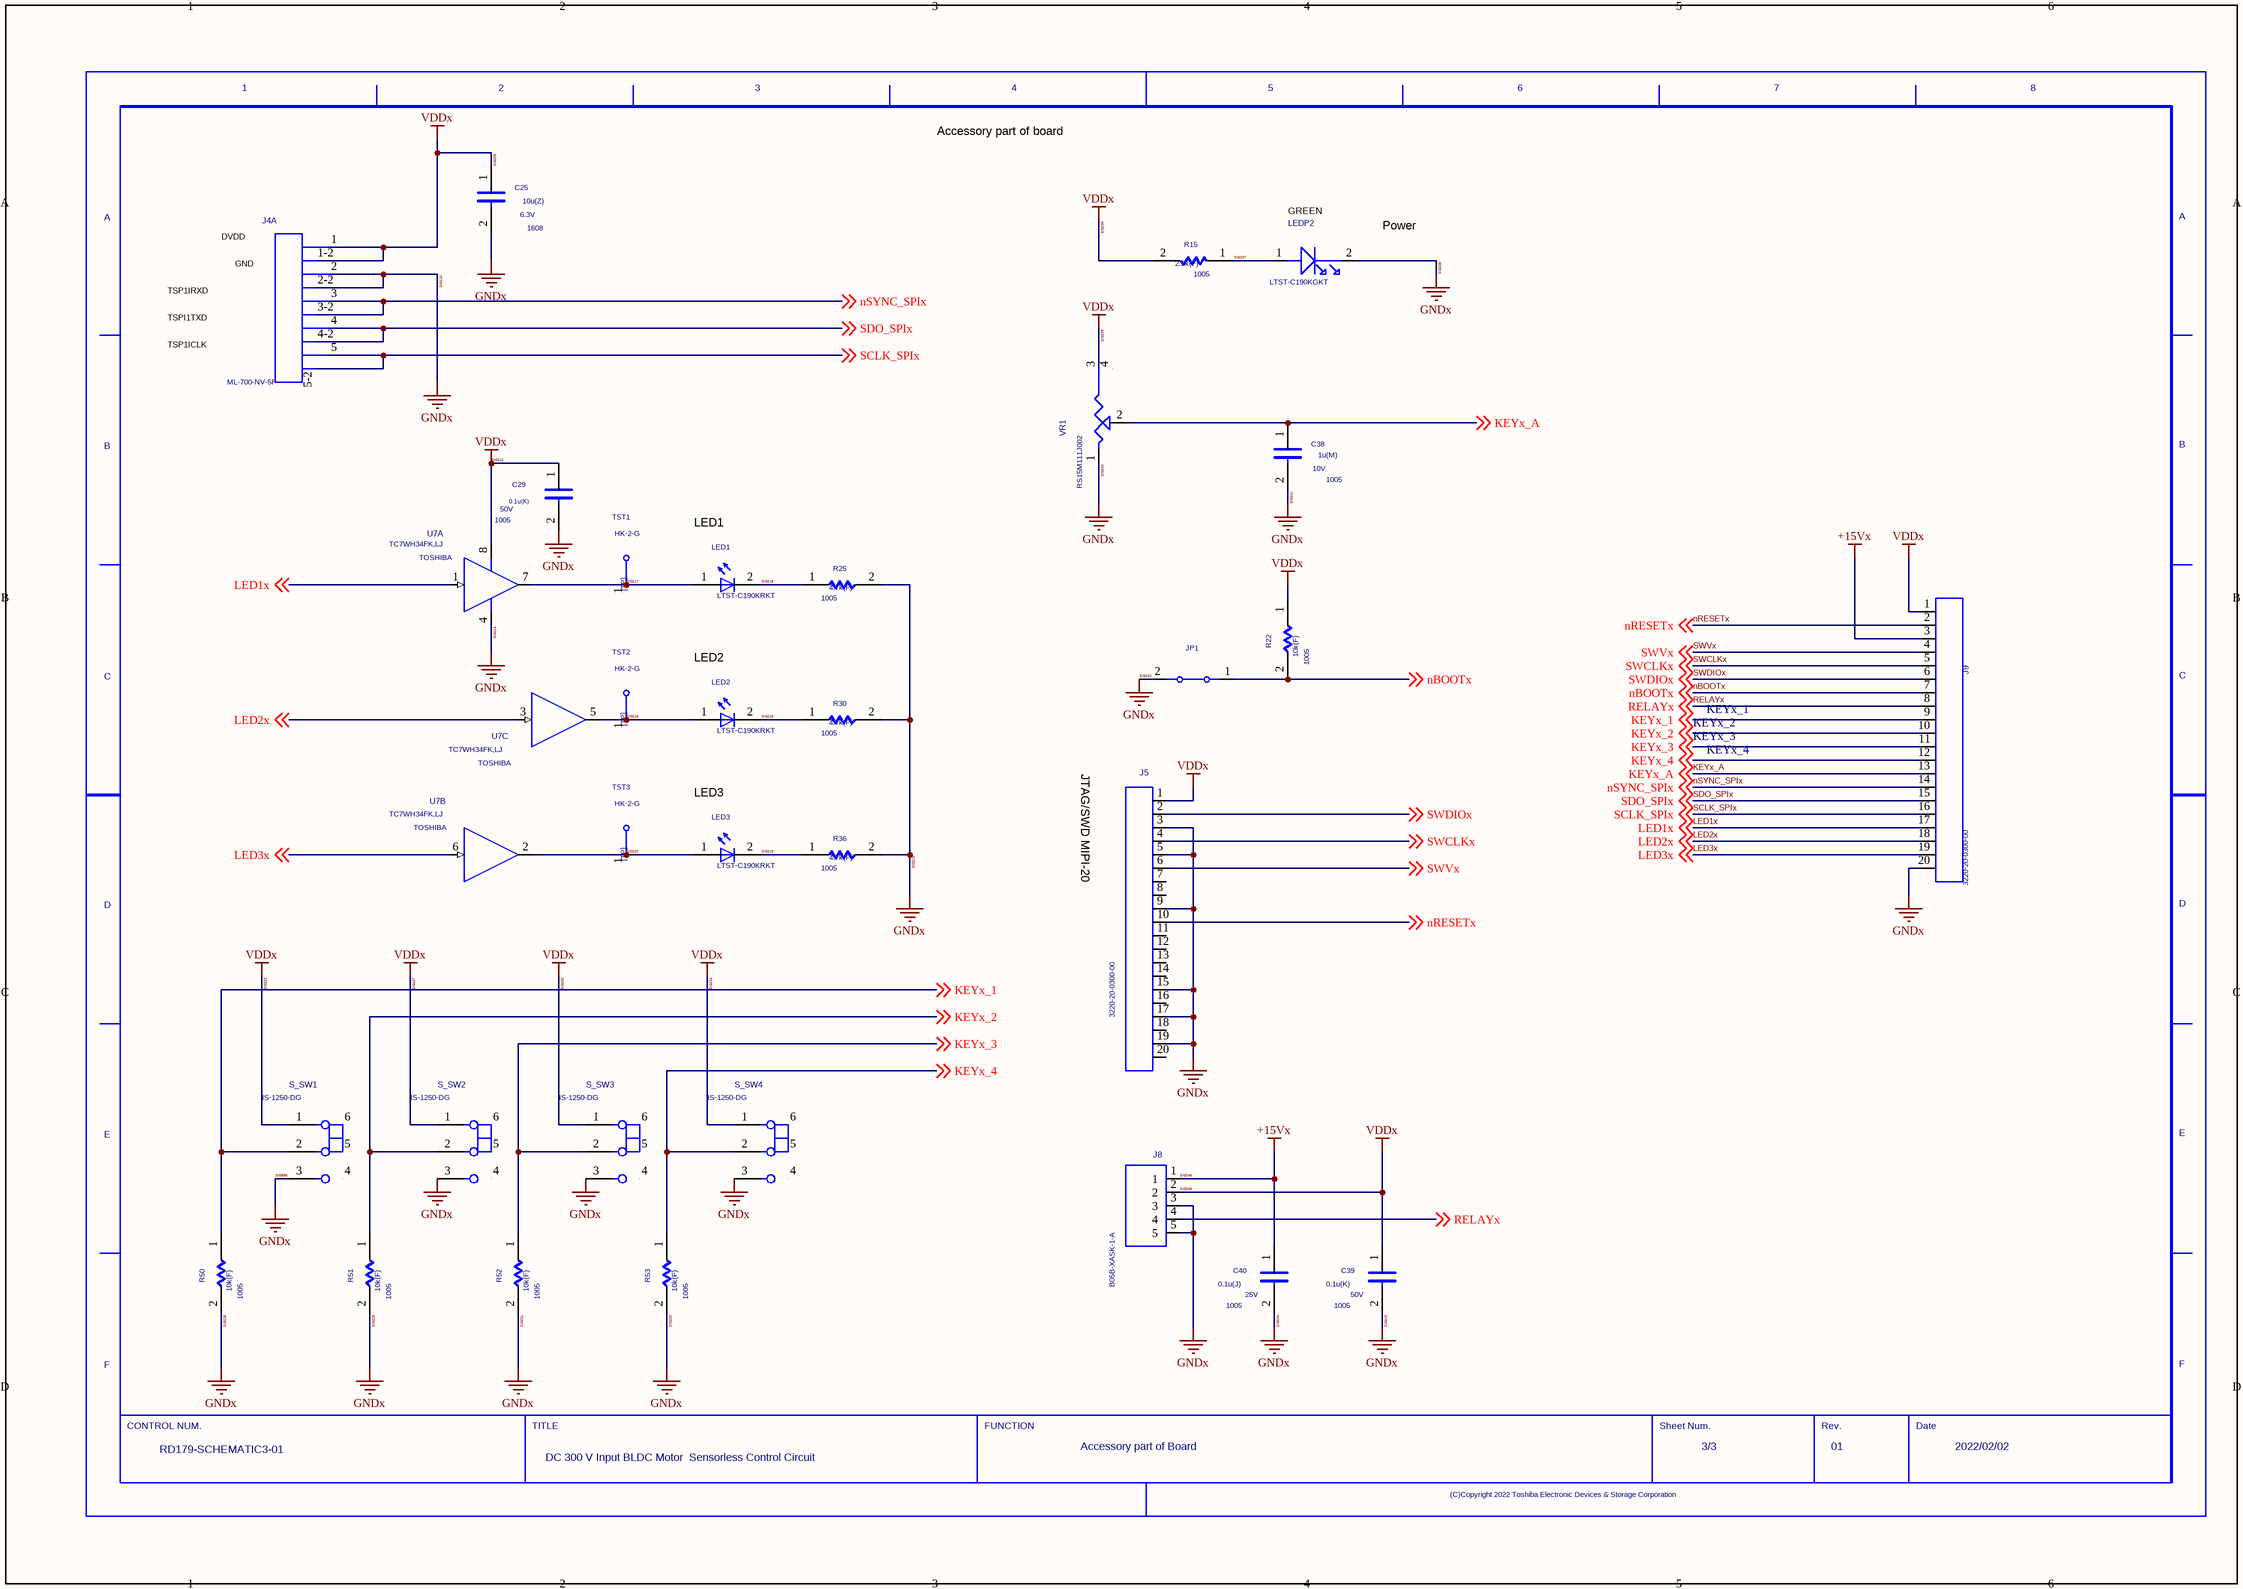
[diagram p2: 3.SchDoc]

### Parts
(Parts that share a designator on the sheet are numbered #1, #2 ... from top to bottom, then left to right.)
C25  SIZECODESMD: 1608  VAL2: 6.3V  VAL1: 10u(Z)  (hidden comment: C)
C29  SIZECODESMD: 1005  VAL2: 50V  VAL1: 0.1u(K)  (hidden comment: C)
C38  SIZECODESMD: 1005  VAL2: 10V  VAL1: 1u(M)  (hidden comment: C)
C39  SIZECODESMD: 1005  VAL2: 50V  VAL1: 0.1u(K)  (hidden comment: C)
C40  SIZECODESMD: 1005  VAL2: 25V  VAL1: 0.1u(J)  (hidden comment: C)
J4  VAL3: ML-700-NV-5P  (hidden comment: ML_700_NH_5P)  (part A of 3)
J5  3220-20-0300-00
J8  B05B-XASK-1-A
J9  3220-20-0300-00
JP1  JP  (value not drawn)
LED1  VAL3: LTST-C190KRKT  (hidden comment: LED)
LED2  VAL3: LTST-C190KRKT  (hidden comment: LED)
LED3  VAL3: LTST-C190KRKT  (hidden comment: LED)
LEDP2  LTST-C190KGKT  [LED]
R15  SIZECODESMD: 1005  VAL1: 2.2k(F)  (hidden comment: R)
R22  SIZECODESMD: 1005  VAL1: 10k(F)  (hidden comment: R)
R25  SIZECODESMD: 1005  VAL1: 4.7k(F)  (hidden comment: R)
R30  SIZECODESMD: 1005  VAL1: 4.7k(F)  (hidden comment: R)
R36  SIZECODESMD: 1005  VAL1: 4.7k(F)  (hidden comment: R)
R50  SIZECODESMD: 1005  VAL1: 10k(F)  (hidden comment: R)
R51  SIZECODESMD: 1005  VAL1: 10k(F)  (hidden comment: R)
R52  SIZECODESMD: 1005  VAL1: 10k(F)  (hidden comment: R)
R53  SIZECODESMD: 1005  VAL1: 10k(F)  (hidden comment: R)
S_SW1  VAL3: IS-1250-DG  (hidden comment: SW_IS_1250)
S_SW2  VAL3: IS-1250-DG  (hidden comment: SW_IS_1250)
S_SW3  VAL3: IS-1250-DG  (hidden comment: SW_IS_1250)
S_SW4  VAL3: IS-1250-DG  (hidden comment: SW_IS_1250)
TST1  VAL3: HK-2-G  (hidden comment: TP)
TST2  VAL3: HK-2-G  (hidden comment: TP)
TST3  VAL3: HK-2-G  (hidden comment: TP)
U7  USERCOMPTEXT3: TOSHIBA  VAL3: TC7WH34FK,LJ  (hidden comment: SN74LVC3G17DCUR_1)  (parts A,B,C of 3)
U?#3  DATE: 2022/02/02  TITLE: DC 300 V Input BLDC Motor / Sensorless Control Circuit  DRAWINGNUMBER: RD179-SCHEMATIC3-01  FUNCTION: Accessory part of Board  SHEETNUMBER: 3/3  REVISION: 01  (hidden comment: WAKU_DEF100)
VR1  VAL3: RS15M111J002  (hidden comment: VR)

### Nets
SIG209: C25.1 C29.1 C39.1 J4.1 J4.1-2 J5.1 J8.2 J9.1 R15.2 R22.1 S_SW1.1 S_SW2.1 S_SW3.1 S_SW4.1 U7.8(+3.3) VR1.3(B)  [also labelled SIG212, SIG223, SIG227, SIG230, SIG234, SIG236, SIG239, SIG245, VDDx]
SIG210: C25.2 C29.2 C38.2 C39.2 C40.2 J4.2 J4.2-2 J5.3 J5.5 J5.9 J5.15 J5.17 J5.19 J8.3 J8.5 J9.20 JP1.2 LEDP2.2(Cathode) R25.2 R30.2 R36.2 R50.2 R51.2 R52.2 R53.2 S_SW1.3 S_SW2.3 S_SW3.3 S_SW4.3 U7.4(GND) VR1.1(A)  [also labelled GNDx, SIG213, SIG214, SIG225, SIG228, SIG231, SIG233, SIG238, SIG240, SIG241, SIG242, SIG243, SIG244, SIG555]
SIG246: C40.1 J8.1 J9.3  [also labelled +15Vx]
KEYx_1: J9.9 R50.1 S_SW1.2 ; off-sheet KEYx_1
KEYx_2: J9.10 R51.1 S_SW2.2 ; off-sheet KEYx_2
KEYx_3: J9.11 R52.1 S_SW3.2 ; off-sheet KEYx_3
KEYx_4: J9.12 R53.1 S_SW4.2 ; off-sheet KEYx_4
KEYx_A: C38.1 J9.13 VR1.2(WIPER) ; off-sheet KEYx_A
LED1x: J9.17 U7.1(INA) ; off-sheet LED1x
LED2x: J9.18 U7.3 ; off-sheet LED2x
LED3x: J9.19 U7.6 ; off-sheet LED3x
nBOOTx: J9.7 JP1.1 R22.2 ; off-sheet nBOOTx
nRESETx: J5.10 J9.2 ; off-sheet nRESETx
nSYNC_SPIx: J4.3 J4.3-2 J9.14 ; off-sheet nSYNC_SPIx
RELAYx: J8.4 J9.8 ; off-sheet RELAYx
SCLK_SPIx: J4.5 J4.5-2 J9.16 ; off-sheet SCLK_SPIx
SDO_SPIx: J4.4 J4.4-2 J9.15 ; off-sheet SDO_SPIx
SIG215: LED2.2(C) R30.1
SIG216: LED2.1(A) TST2.1 U7.5
SIG217: LED1.1(A) TST1.1 U7.7(OUTY)
SIG218: LED1.2(C) R25.1
SIG219: LED3.2(C) R36.1
SIG220: LED3.1(A) TST3.1 U7.2
SIG237: LEDP2.1(Anode) R15.1
SWCLKx: J5.4 J9.5 ; off-sheet SWCLKx
SWDIOx: J5.2 J9.6 ; off-sheet SWDIOx
SWVx: J5.6 J9.4 ; off-sheet SWVx

Not connected (* = marked no-connect by the designer): J5 7 8 11 12 13 14 16 18 20; S_SW1 4 5 6; S_SW2 4 5 6; S_SW3 4 5 6; S_SW4 4 5 6; VR1 4

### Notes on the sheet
- Accessory part of board
- DVDD
- (near LEDP2) GREEN
- (near LEDP2) Power
- TSPI1TXD
- TSP1IRXD
- GND
- TSP1ICLK
- LED1
- LED2
- KEYx_2
- KEYx_1
- LED3
- JTAG/SWD MIPI-20
- KEYx_3
- KEYx_4

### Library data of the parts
C25 = C: as C5 on sheet 1
C29 C38-C40 = C: as C3 on sheet 1
J4 = ML_700_NH_5P: COMP: ML-700-NV-5P_R00; TIME: 16:32:00; UPDATEUSER: t5459927; UPDATETIME: 14:23:35; SAVECOUNT: 6; SAVEAREA0: -56271,-34402,27424,4178; OriginalSymbolOrigin: (0,0)
J5 = CON20: COMP: 3220-20-0300-00_R00; TIME: 16:32:01; UPDATEUSER: t5459927; SAVECOUNT: 1; SAVEAREA0: -36272,-54408,42011,2984; OriginalSymbolOrigin: (0,0); INSTANCENAME: I16846450
J8 = B05B_XASK_1_A: COMP: B05B-XASK-1-A_R00; TIME: 16:31:59; UPDATEUSER: t5459927; SAVECOUNT: 1; SAVEAREA0: -8887,-15544,13478,852; OriginalSymbolOrigin: (0,0); INSTANCENAME: I16947079
J9 = CON20: COMP: 3220-20-0300-00_R00; TIME: 16:32:01; UPDATEUSER: t5459927; SAVECOUNT: 1; SAVEAREA0: -36272,-54408,42011,2984; OriginalSymbolOrigin: (0,0); INSTANCENAME: I17018983
JP1 = JP: OriginalSymbolOrigin: (2540,5080); VAL3: PH-1x40SG; COMP: PH-1X02SG_R00
LED1-LED3 = LED: SAVEAREA0: -6799,-183,19247,15664; TIME: 14:49:55; UPDATEUSER: fukuda-y; UPDATETIME: 13:54:07; SAVECOUNT: 4; OriginalSymbolOrigin: (5080,7620); COMP: LTST-C190_R00
LEDP2 = LED_3RED: COMP: LTST-C190_R00; TIME: 16:32:00; UPDATEUSER: t5459927; SAVECOUNT: 1; OriginalSymbolOrigin: (0,0); INSTANCENAME: I16847094
R15 R22 R50-R53 = R: as R16 on sheet 1
R25 R30 R36 = R: as R5 on sheet 1
S_SW1-S_SW4 = SW_IS_1250: COMP: IS-1250_R00; TIME: 16:32:00; UPDATEUSER: t5459927; UPDATETIME: 08:47:03; SAVECOUNT: 3; SAVEAREA0: -34974,-23415,45046,13471; OriginalSymbolOrigin: (-2540,0)
TST1-TST3 = TP: as TP1 on sheet 1
U7 = SN74LVC3G17DCUR_1: COMP: TC7WH34FK; ORDER: 0; TIME: 16:32:01; UPDATEUSER: t5459927; UPDATETIME: 15:47:45; SAVECOUNT: 5; SAVEAREA0: -11904,-17167,21643,7427; OriginalSymbolOrigin: (0,0); CaptureCellPackProp: SN74LVC3G17DCUR_1A; FUNCN: TC7WH34FK_LJ_1
U?#3 = WAKU_DEF100: PLOTTIME: HH:MM; SAVEAREA0: 147884,-66467,487065,89883; TIME: 14:30:25; UPDATEUSER: t5459927; UPDATETIME: 12:53:05; SAVECOUNT: 7; OriginalSymbolOrigin: (10160,284480)
VR1 = VR: COMP: RS15M111J002_R00; TIME: 16:32:00; UPDATEUSER: t5459927; UPDATETIME: 09:39:06; SAVECOUNT: 2; SAVEAREA0: -14973,-11876,27253,11499; OriginalSymbolOrigin: (0,0)

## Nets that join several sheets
SIG369: 1 (19 pins), 2 (J7.1 R13.2 R54.1)
SIG371: 1 (25 pins), 2 (9 pins)
SIG376: 1 (16 pins), 2 (10 pins)
SIG462: 1 (C19.1 J3.1 J6.3), 2 (C1.1 C2.1 U9.5)
SIG477: 1 (5 pins), 2 (U9.23 U9.24)
SIG526: 1 (9 pins), 2 (C11.2 R6.1 U6.4)
SIG567: 1 (6 pins), 2 (7 pins)
AD_UP_1: 1 (U2.32 U8.4), 2 (C30.1 R29.1 TP10.1)
AD_VP_1: 1 (U2.33 U8.6), 2 (C33.1 R39.1 TP12.1)
AD_WP_1: 1 (U2.34 U8.8), 2 (C34.1 R46.1 TP13.1)
COMMD: 1 (J6.10 R18.6 U2.40), 2 (J7.6)
DIAG: 1 (R43.1), 2 (U9.4)
GPIO_MAIN: 1 (U2.18), 2 (J7.8)
KEY_1: 1 (J6.9 R18.5 U2.41), 2 (J7.5)
nSD: 1 (U2.19), 2 (R13.1 U9.7)
RXD_UA_MCU: 1 (U2.17), 2 (J7.3)
SIG571: 1 (U5.2), 2 (J7.7 R54.2)
TXD_UA_MCU: 1 (U2.16), 2 (J7.4)
UH_1: 1 (TP5.1 U2.1), 2 (U9.15)
UL_1: 1 (TP14.1 U2.2), 2 (U9.12)
VH_1: 1 (TP4.1 U2.3), 2 (U9.14)
VL_1: 1 (TP15.1 U2.4), 2 (U9.11)
WH_1: 1 (TP3.1 U2.5), 2 (U9.13)
WL_1: 1 (TP16.1 U2.6), 2 (U9.10)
